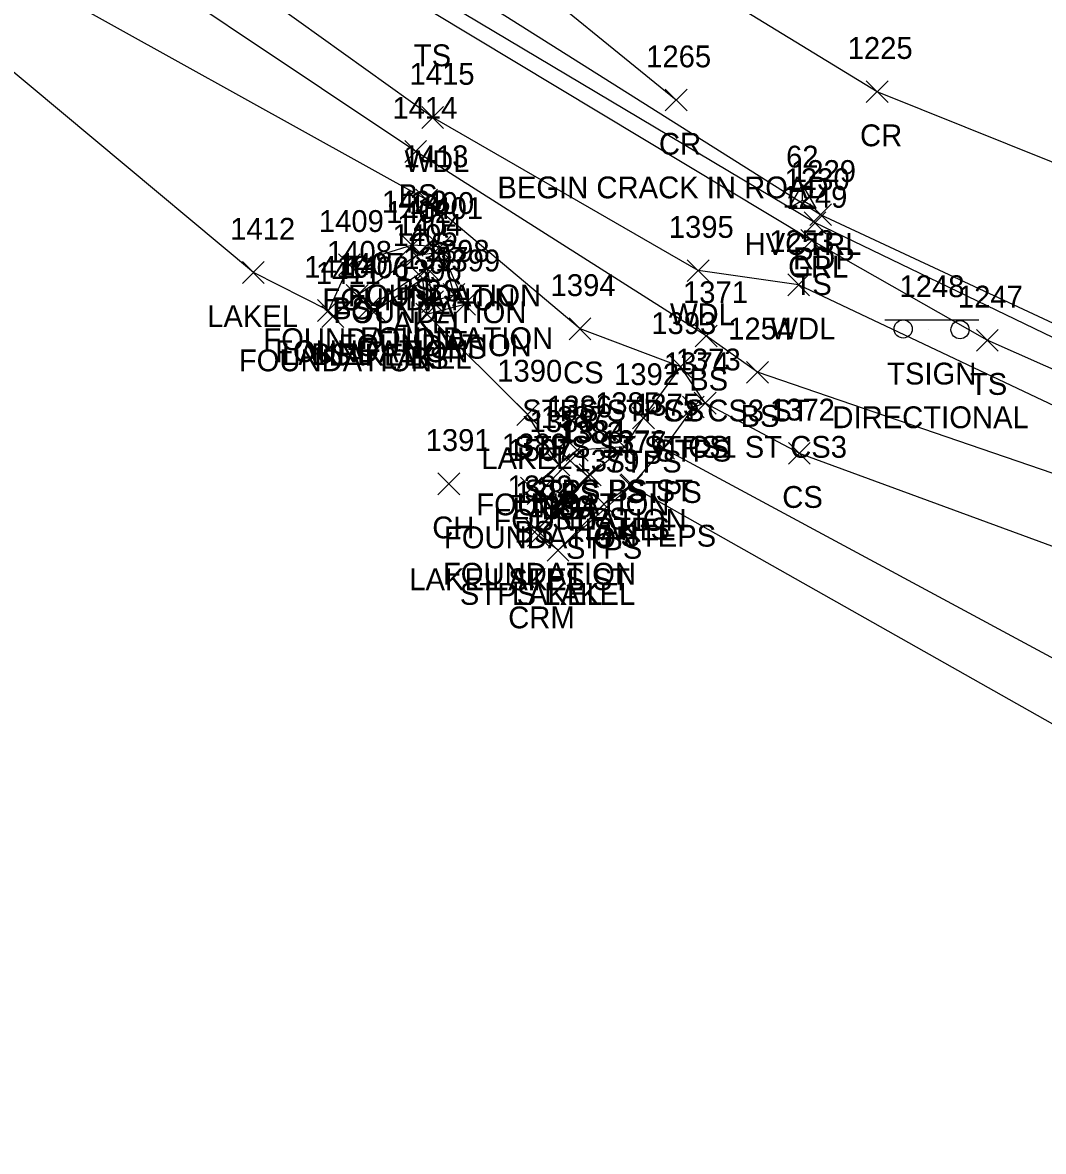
# Model space of a CAD drawing. Extents: x 1401404 to 1403982, y 557481 to 559873.
# Drawn here: x 1403210.7 to 1403304.1, y 558534.5 to 558637.9 of the extents above; entities that cross this region are included whole.
import ezdxf

# ---------------------------------------------------------------- set-up
doc = ezdxf.new("R2010")
doc.units = 0
for name, color, linetype in [('C_A', 7, 'Continuous'), ('C_I', 7, 'Continuous'), ('CPSM', 7, 'Continuous'), ('L_A', 7, 'Continuous'), ('L_C', 7, 'Continuous'), ('L_I', 7, 'Continuous'), ('L_TIC', 7, 'Continuous'), ('LAWA', 7, 'Continuous'), ('LAWE', 7, 'Continuous'), ('LBC', 7, 'Continuous'), ('LBF', 7, 'Continuous'), ('LELB', 7, 'Continuous'), ('P_A', 7, 'Continuous'), ('P_C', 7, 'Continuous'), ('P_I', 7, 'Continuous'), ('P_TIC', 7, 'Continuous'), ('PET', 7, 'Continuous'), ('PRC', 7, 'Continuous'), ('R_A', 7, 'Continuous'), ('R_I', 7, 'Continuous'), ('R_TIC', 7, 'Continuous'), ('RGR', 7, 'Continuous'), ('S_A', 7, 'Continuous'), ('S_C', 7, 'Continuous'), ('S_I', 7, 'Continuous'), ('SSGN', 7, 'Continuous')]:
    doc.layers.add(name, color=color, linetype=linetype)

msp = doc.modelspace()

# ---------------------------------------------------------------- linework, layer by layer
at = {"layer": 'CPSM'}
for p, q in [((1403280.84, 558620.92), (1403282.09, 558623.09)), ((1403283.34, 558620.92), (1403282.09, 558623.09)), ((1403282.09, 558621.65), (1403282.09, 558623.09)), ((1403280.84, 558620.92), (1403282.09, 558621.65)), ((1403282.09, 558621.65), (1403282.09, 558621.65)), ((1403282.09, 558621.65), (1403283.34, 558620.92)), ((1403280.84, 558620.92), (1403283.34, 558620.92))]:
    msp.add_line(p, q, dxfattribs=at)
at = {"layer": 'L_TIC'}
for points in [[(1403247.23, 558628.23), (1403249.23, 558630.23)], [(1403249.23, 558628.23), (1403247.23, 558630.23)], [(1403245.67, 558625.12), (1403247.67, 558627.12)], [(1403247.67, 558625.12), (1403245.67, 558627.12)], [(1403246.68, 558620.68), (1403248.68, 558622.68)], [(1403248.68, 558620.68), (1403246.68, 558622.68)], [(1403245.35, 558616.53), (1403247.35, 558618.53)], [(1403247.35, 558616.53), (1403245.35, 558618.53)], [(1403247.92, 558616.4), (1403249.92, 558618.4)], [(1403249.92, 558616.4), (1403247.92, 558618.4)], [(1403281.94, 558616.97), (1403283.94, 558618.97)], [(1403283.94, 558616.97), (1403281.94, 558618.97)], [(1403245.73, 558615.58), (1403247.73, 558617.58)], [(1403247.73, 558615.58), (1403245.73, 558617.58)], [(1403248.09, 558615.93), (1403250.09, 558617.93)], [(1403250.09, 558615.93), (1403248.09, 558617.93)], [(1403230.81, 558614.04), (1403232.81, 558616.04)], [(1403232.81, 558614.04), (1403230.81, 558616.04)], [(1403239.59, 558614.75), (1403241.59, 558616.75)], [(1403241.59, 558614.75), (1403239.59, 558616.75)], [(1403246.74, 558614.4), (1403248.74, 558616.4)], [(1403248.74, 558614.4), (1403246.74, 558616.4)], [(1403271.54, 558614.21), (1403273.54, 558616.21)], [(1403273.54, 558614.21), (1403271.54, 558616.21)], [(1403246.34, 558613.46), (1403248.34, 558615.46)], [(1403248.34, 558613.46), (1403246.34, 558615.46)], [(1403249.18, 558612.02), (1403251.18, 558614.02)], [(1403251.18, 558612.02), (1403249.18, 558614.02)], [(1403280.73, 558612.91), (1403282.73, 558614.91)], [(1403282.73, 558612.91), (1403280.73, 558614.91)], [(1403240.32, 558611.93), (1403242.32, 558613.93)], [(1403242.32, 558611.93), (1403240.32, 558613.93)], [(1403247.23, 558611.37), (1403249.23, 558613.37)], [(1403249.23, 558611.37), (1403247.23, 558613.37)], [(1403247.23, 558611.37), (1403249.23, 558613.37)], [(1403249.23, 558611.37), (1403247.23, 558613.37)], [(1403250.16, 558611.14), (1403252.16, 558613.14)], [(1403252.16, 558611.14), (1403250.16, 558613.14)], [(1403237.68, 558610.56), (1403239.68, 558612.56)], [(1403239.68, 558610.56), (1403237.68, 558612.56)], [(1403237.68, 558610.56), (1403239.68, 558612.56)], [(1403239.68, 558610.56), (1403237.68, 558612.56)], [(1403238.09, 558609.99), (1403240.09, 558611.99)], [(1403240.09, 558609.99), (1403238.09, 558611.99)], [(1403241.42, 558610.82), (1403243.42, 558612.82)], [(1403243.42, 558610.82), (1403241.42, 558612.82)], [(1403241.95, 558610.51), (1403243.95, 558612.51)], [(1403243.95, 558610.51), (1403241.95, 558612.51)], [(1403246.69, 558610.22), (1403248.69, 558612.22)], [(1403248.69, 558610.22), (1403246.69, 558612.22)], [(1403246.69, 558610.22), (1403248.69, 558612.22)], [(1403248.69, 558610.22), (1403246.69, 558612.22)], [(1403260.72, 558608.88), (1403262.72, 558610.88)], [(1403262.72, 558608.88), (1403260.72, 558610.88)], [(1403272.27, 558608.23), (1403274.27, 558610.23)], [(1403274.27, 558608.23), (1403272.27, 558610.23)], [(1403298, 558607.83), (1403300, 558609.83)], [(1403300, 558607.83), (1403298, 558609.83)], [(1403269.93, 558605.4), (1403271.93, 558607.4)], [(1403271.93, 558605.4), (1403269.93, 558607.4)], [(1403269.93, 558605.4), (1403271.93, 558607.4)], [(1403271.93, 558605.4), (1403269.93, 558607.4)], [(1403269.93, 558605.4), (1403271.93, 558607.4)], [(1403271.93, 558605.4), (1403269.93, 558607.4)], [(1403276.97, 558604.9), (1403278.97, 558606.9)], [(1403278.97, 558604.9), (1403276.97, 558606.9)], [(1403271.09, 558601.72), (1403273.09, 558603.72)], [(1403273.09, 558601.72), (1403271.09, 558603.72)], [(1403272.17, 558602.07), (1403274.17, 558604.07)], [(1403274.17, 558602.07), (1403272.17, 558604.07)], [(1403272.17, 558602.07), (1403274.17, 558604.07)], [(1403274.17, 558602.07), (1403272.17, 558604.07)], [(1403272.17, 558602.07), (1403274.17, 558604.07)], [(1403274.17, 558602.07), (1403272.17, 558604.07)], [(1403255.92, 558601.04), (1403257.92, 558603.04)], [(1403257.92, 558601.04), (1403255.92, 558603.04)], [(1403266.52, 558600.72), (1403268.52, 558602.72)], [(1403268.52, 558600.72), (1403266.52, 558602.72)], [(1403260.46, 558597.76), (1403262.46, 558599.76)], [(1403262.46, 558597.76), (1403260.46, 558599.76)], [(1403264.79, 558598.07), (1403266.79, 558600.07)], [(1403266.79, 558598.07), (1403264.79, 558600.07)], [(1403264.79, 558598.07), (1403266.79, 558600.07)], [(1403266.79, 558598.07), (1403264.79, 558600.07)], [(1403268.36, 558597.93), (1403270.36, 558599.93)], [(1403270.36, 558597.93), (1403268.36, 558599.93)], [(1403280.79, 558597.48), (1403282.79, 558599.48)], [(1403282.79, 558597.48), (1403280.79, 558599.48)], [(1403259.82, 558596.8), (1403261.82, 558598.8)], [(1403261.82, 558596.8), (1403259.82, 558598.8)], [(1403258.77, 558596.42), (1403260.77, 558598.42)], [(1403260.77, 558596.42), (1403258.77, 558598.42)], [(1403258.77, 558596.42), (1403260.77, 558598.42)], [(1403260.77, 558596.42), (1403258.77, 558598.42)], [(1403261.64, 558595.5), (1403263.64, 558597.5)], [(1403263.64, 558595.5), (1403261.64, 558597.5)], [(1403248.71, 558594.69), (1403250.71, 558596.69)], [(1403250.71, 558594.69), (1403248.71, 558596.69)], [(1403261.4, 558595.38), (1403263.4, 558597.38)], [(1403263.4, 558595.38), (1403261.4, 558597.38)], [(1403265.36, 558594.5), (1403267.36, 558596.5)], [(1403267.36, 558594.5), (1403265.36, 558596.5)], [(1403265.45, 558594.59), (1403267.45, 558596.59)], [(1403267.45, 558594.59), (1403265.45, 558596.59)], [(1403256.26, 558594.28), (1403258.26, 558596.28)], [(1403258.26, 558594.28), (1403256.26, 558596.28)], [(1403256.87, 558593.78), (1403258.87, 558595.78)], [(1403258.87, 558593.78), (1403256.87, 558595.78)], [(1403262.91, 558592.82), (1403264.91, 558594.82)], [(1403264.91, 558592.82), (1403262.91, 558594.82)], [(1403256.77, 558590.45), (1403258.77, 558592.45)], [(1403258.77, 558590.45), (1403256.77, 558592.45)], [(1403256.9, 558589.94), (1403258.9, 558591.94)], [(1403258.9, 558589.94), (1403256.9, 558591.94)], [(1403256.9, 558589.94), (1403258.9, 558591.94)], [(1403258.9, 558589.94), (1403256.9, 558591.94)], [(1403258.7, 558588.6), (1403260.7, 558590.6)], [(1403260.7, 558588.6), (1403258.7, 558590.6)], [(1403258.7, 558588.6), (1403260.7, 558590.6)], [(1403260.7, 558588.6), (1403258.7, 558590.6)]]:
    msp.add_lwpolyline(points, dxfattribs=at)
at = {"layer": 'LAWA'}
msp.add_lwpolyline([(1403316.66, 558597.36), (1403281.73, 558613.91), (1403272.54, 558615.21), (1403248.23, 558629.23), (1403213.48, 558654.18), (1403180.64, 558681.31), (1403143.75, 558710.34), (1403107.91, 558739.1), (1403071.69, 558772.58), (1403068.31, 558766.93), (1403071.88, 558756.66), (1403070.51, 558749.44)], dxfattribs=at)
at = {"layer": 'LAWE'}
for points in [[(1403238.68, 558611.56), (1403231.81, 558615.04), (1403202.57, 558639.47), (1403173.17, 558667.73), (1403127.98, 558695.57), (1403090.18, 558721.43), (1403068.99, 558749.07), (1403055.64, 558748.74), (1403047.53, 558763.16), (1403042.82, 558768.94)], [(1403259.77, 558597.42), (1403256.92, 558602.04), (1403247.69, 558611.22), (1403247.34, 558614.46), (1403242.95, 558611.51)], [(1403696.34, 558534.54), (1403680.72, 558542.26), (1403669.4, 558548.58), (1403629.67, 558556.01), (1403603.5, 558551.35), (1403567.18, 558559.29), (1403520.13, 558560.76), (1403486.9, 558558.65), (1403434.25, 558550.99), (1403410.67, 558547.97), (1403397.83, 558540.52), (1403383.21, 558537.84), (1403361.63, 558542.24), (1403347.73, 558548.91), (1403330.86, 558557.2), (1403312.09, 558569.67), (1403266.36, 558595.5), (1403259.7, 558589.6), (1403257.9, 558590.94)]]:
    msp.add_lwpolyline(points, dxfattribs=at)
at = {"layer": 'LBC'}
for points in [[(1403248.23, 558612.37), (1403250.18, 558613.02), (1403249.09, 558616.93), (1403246.73, 558616.58), (1403241.32, 558612.93), (1403239.09, 558610.99)], [(1403248.23, 558612.37), (1403247.74, 558615.4), (1403242.42, 558611.82)], [(1403257.77, 558591.45), (1403262.4, 558596.38), (1403260.82, 558597.8), (1403257.87, 558594.78)]]:
    msp.add_lwpolyline(points, dxfattribs=at)
at = {"layer": 'LBF'}
for points in [[(1403257.9, 558590.94), (1403262.64, 558596.5), (1403265.79, 558599.07), (1403267.52, 558601.72), (1403270.93, 558606.4)], [(1403273.17, 558603.07), (1403270.93, 558606.4)], [(1403273.17, 558603.07), (1403272.09, 558602.72), (1403269.36, 558598.93), (1403266.45, 558595.59), (1403263.91, 558593.82), (1403259.7, 558589.6)]]:
    msp.add_lwpolyline(points, dxfattribs=at)
at = {"layer": 'LELB'}
for points in [[(1403567.19, 558568.67), (1403521.33, 558570.05), (1403484.77, 558571.48), (1403436.83, 558574.71), (1403390.35, 558579.88), (1403360.17, 558585.19), (1403345.93, 558587.28), (1403333.51, 558592.26), (1403317.51, 558600.62), (1403299, 558608.83), (1403282.94, 558617.97), (1403248.09, 558638.93), (1403217.12, 558660.94), (1403185.33, 558684.7), (1403148.79, 558715.46), (1403112.06, 558744.49), (1403074.23, 558776.66), (1403055.65, 558783.75), (1403043.18, 558796.21), (1403041.06, 558801.07)], [(1403270.93, 558606.4), (1403261.72, 558609.88), (1403247.68, 558621.68), (1403207.96, 558643.77), (1403210.15, 558647.44), (1403209.07, 558648.44), (1403205.58, 558645.65), (1403178.43, 558674.04), (1403139.41, 558704.55), (1403100.63, 558728.29)], [(1403246.67, 558626.12), (1403212.22, 558649.17)], [(1403341.76, 558583.81), (1403338.8, 558584.67), (1403330.23, 558588.71), (1403320.84, 558584.14), (1403323.37, 558590.35), (1403277.97, 558605.9), (1403273.27, 558609.23), (1403246.67, 558626.12)], [(1403247.69, 558611.22), (1403251.16, 558612.14), (1403248.92, 558617.4), (1403246.35, 558617.53), (1403240.59, 558615.75), (1403238.68, 558611.56)], [(1403281.79, 558598.48), (1403273.17, 558603.07)], [(1403265.79, 558599.07), (1403261.46, 558598.76), (1403259.77, 558597.42), (1403257.26, 558595.28)], [(1403320.97, 558571.12), (1403269.36, 558598.93)], [(1403281.79, 558598.48), (1403320.84, 558584.14)]]:
    msp.add_lwpolyline(points, dxfattribs=at)
at = {"layer": 'P_TIC'}
for points in [[(1403287.92, 558630.6), (1403289.92, 558632.6)], [(1403289.92, 558630.6), (1403287.92, 558632.6)], [(1403269.51, 558629.83), (1403271.51, 558631.83)], [(1403271.51, 558629.83), (1403269.51, 558631.83)], [(1403282.74, 558619.33), (1403284.74, 558621.33)], [(1403284.74, 558619.33), (1403282.74, 558621.33)]]:
    msp.add_lwpolyline(points, dxfattribs=at)
at = {"layer": 'PET'}
msp.add_lwpolyline([(1403567.32, 558571.16), (1403521.05, 558571.89), (1403485.08, 558573.95), (1403437.34, 558577.29), (1403390.93, 558583.55), (1403361.61, 558591.03), (1403321.82, 558602.54), (1403283.74, 558620.33), (1403244.19, 558645.3), (1403219.22, 558663.61), (1403205.44, 558672.12), (1403186.06, 558688.41), (1403150.64, 558718.11), (1403114.18, 558748.06), (1403076.2, 558780.03), (1403043.94, 558806.7), (1402997.13, 558841.77), (1402954.25, 558870.69), (1402915.87, 558893.53), (1402876.18, 558915.42), (1402801.33, 558955.21), (1402766.49, 558972.95)], dxfattribs=at)
at = {"layer": 'PRC'}
for points in [[(1403567.87, 558582.77), (1403521.72, 558584.55), (1403486.23, 558585.01), (1403438.97, 558588.43), (1403393.1, 558594.9), (1403360.83, 558602.71), (1403288.92, 558631.6), (1403250.3, 558655.21), (1403225.89, 558672.35), (1403193.37, 558698.04), (1403157.15, 558726.96), (1403121.95, 558757.26), (1403083.22, 558789.98), (1403051.1, 558815.94), (1403004.27, 558851.49), (1402960.21, 558880.82), (1402921.63, 558903.82), (1402881.32, 558926.06), (1402807.32, 558964.73), (1402770.83, 558983.44)], [(1403270.51, 558630.83), (1403254.38, 558643.97), (1403247.18, 558647.74), (1403222.07, 558666.96), (1403211.27, 558674.34), (1403200.12, 558681.7), (1403193.45, 558684.38)]]:
    msp.add_lwpolyline(points, dxfattribs=at)
at = {"layer": 'R_TIC'}
for points in [[(1403282.23, 558618.58), (1403284.23, 558620.58)], [(1403284.23, 558618.58), (1403282.23, 558620.58)]]:
    msp.add_lwpolyline(points, dxfattribs=at)
at = {"layer": 'RGR'}
msp.add_lwpolyline([(1403343.04, 558588.83), (1403321.63, 558601.07), (1403283.23, 558619.58), (1403243.1, 558643.52), (1403218.12, 558661.74), (1403185.48, 558687.65), (1403149.87, 558716.9), (1403113.35, 558746.32), (1403075.03, 558778.37), (1403064.92, 558785.89), (1403057.13, 558787.17)], dxfattribs=at)
at = {"layer": 'SSGN'}
for p, q in [((1403289.63, 558610.7), (1403298.23, 558610.7)), ((1403293.66, 558609.8), (1403293.66, 558609.8))]:
    msp.add_line(p, q, dxfattribs=at)
for centre in [(1403291.3, 558609.87), (1403296.51, 558609.8)]:
    msp.add_circle(centre, 0.833, dxfattribs=at)

# ---------------------------------------------------------------- texts
at = {"layer": 'C_A'}
msp.add_text('HVCTRL', height=2, dxfattribs=at).set_placement((1403276.78, 558616.65))
at = {"layer": 'C_I'}
msp.add_text('62', height=2, dxfattribs=at).set_placement((1403280.58, 558624.65))
at = {"layer": 'L_A'}
for s, p in [('TS', (1403246.5, 558633.93)), ('WDL', (1403245.65, 558624.23)), ('BS', (1403245.11, 558621.12)), ('CS', (1403246.12, 558616.68)), ('TS', (1403281.35, 558612.97)), ('FOUNDATION', (1403240.48, 558611.93)), ('BS', (1403244.79, 558612.53)), ('BS', (1403247.36, 558612.4)), ('FOUNDATION', (1403238.13, 558611.58)), ('LAKEL', (1403227.58, 558610.04)), ('BS', (1403239.03, 558610.75)), ('FOUNDATION', (1403239.13, 558610.4)), ('WDL', (1403269.95, 558610.21)), ('LAKEL', (1403243.1, 558609.46)), ('WDL', (1403279.15, 558608.91)), ('FOUNDATION', (1403232.72, 558607.93)), ('FOUNDATION', (1403241.58, 558608.02)), ('FOUNDATION', (1403233.81, 558606.82)), ('FOUNDATION', (1403239.62, 558607.37)), ('FOUNDATION', (1403239.62, 558607.37)), ('BS', (1403249.6, 558607.14)), ('FOUNDATION', (1403230.48, 558605.99)), ('LAKEL', (1403234.44, 558606.56)), ('BS', (1403237.12, 558606.56)), ('LAKEL', (1403238.71, 558606.51)), ('LAKEL', (1403243.46, 558606.22)), ('BS', (1403246.13, 558606.22)), ('CS', (1403260.16, 558604.88)), ('BS', (1403271.71, 558604.23)), ('TS', (1403297.41, 558603.83)), ('STPS STPS1 CS3 ST', (1403256.42, 558601.4)), ('STPS STPS1 CS3 ST', (1403256.42, 558601.4)), ('CS', (1403269.37, 558601.4)), ('BS', (1403276.41, 558600.9)), ('STPS ST STPS1 ST CS3', (1403255.69, 558598.07)), ('STPS ST STPS1 ST CS3', (1403255.69, 558598.07)), ('STPS', (1403268.61, 558597.72)), ('CS', (1403271.61, 558598.07)), ('LAKEL', (1403252.68, 558597.04)), ('STPS', (1403264.04, 558596.72)), ('STPS BS ST', (1403256.6, 558594.07)), ('BS', (1403259.9, 558593.76)), ('BS', (1403264.23, 558594.07)), ('STPS', (1403265.88, 558593.93)), ('CS', (1403280.23, 558593.48)), ('FOUNDATION', (1403252.22, 558592.8)), ('LAKEL', (1403255.54, 558592.42)), ('BS', (1403258.21, 558592.42)), ('FOUNDATION', (1403253.79, 558591.38)), ('STPS', (1403259.16, 558591.5)), ('CH', (1403248.19, 558590.69)), ('BS', (1403255.7, 558590.28)), ('LAKEL', (1403262.12, 558590.5)), ('STPS', (1403262.97, 558590.59)), ('FOUNDATION', (1403249.26, 558589.78)), ('STPS', (1403260.43, 558588.82)), ('FOUNDATION', (1403249.16, 558586.45)), ('LAKEL STPS ST', (1403246.08, 558585.94)), ('LAKEL', (1403253.66, 558585.94)), ('STPS LAKEL', (1403250.71, 558584.6)), ('LAKEL', (1403255.47, 558584.6))]:
    msp.add_text(s, height=2, dxfattribs=at).set_placement(p)
at = {"layer": 'L_C'}
for s, p in [('5 STEPS', (1403263.18, 558589.93)), ('CRM', (1403255.14, 558582.45))]:
    msp.add_text(s, height=2, dxfattribs=at).set_placement(p)
at = {"layer": 'L_I'}
for s, p in [('1415', (1403246.11, 558632.23)), ('1414', (1403244.54, 558629.12)), ('1413', (1403245.55, 558624.68)), ('1403', (1403243.58, 558620.53)), ('1400', (1403246.07, 558620.4)), ('1249', (1403280.24, 558620.97)), ('1402', (1403243.96, 558619.58)), ('1401', (1403246.89, 558619.93)), ('1409', (1403237.81, 558618.75)), ('1404', (1403244.97, 558618.4)), ('1395', (1403269.84, 558618.21)), ('1412', (1403229.69, 558618.04)), ('1405', (1403244.56, 558617.46)), ('1253', (1403279.04, 558616.91)), ('1408', (1403238.55, 558615.93)), ('1397', (1403245.54, 558615.37)), ('1397', (1403245.54, 558615.37)), ('1398', (1403247.49, 558616.02)), ('1399', (1403248.46, 558615.14)), ('1410', (1403236.47, 558614.56)), ('1410', (1403236.47, 558614.56)), ('1407', (1403239.65, 558614.82)), ('1406', (1403240.12, 558614.51)), ('1396', (1403244.94, 558614.22)), ('1396', (1403244.94, 558614.22)), ('1411', (1403237.53, 558613.99)), ('1394', (1403259.02, 558612.88)), ('1371', (1403271.14, 558612.23)), ('1247', (1403296.31, 558611.83)), ('1393', (1403268.24, 558609.4)), ('1393', (1403268.24, 558609.4)), ('1393', (1403268.24, 558609.4)), ('1254', (1403275.28, 558608.9)), ('1374', (1403269.4, 558605.72)), ('1373', (1403270.48, 558606.07)), ('1373', (1403270.48, 558606.07)), ('1373', (1403270.48, 558606.07)), ('1390', (1403254.14, 558605.04)), ('1392', (1403264.83, 558604.72)), ('1386', (1403258.71, 558601.76)), ('1385', (1403263.09, 558602.07)), ('1385', (1403263.09, 558602.07)), ('1375', (1403266.67, 558601.93)), ('1387', (1403258.13, 558600.8)), ('1372', (1403279.1, 558601.48)), ('1388', (1403257.08, 558600.42)), ('1388', (1403257.08, 558600.42)), ('1391', (1403247.58, 558598.69)), ('1383', (1403259.7, 558599.38)), ('1384', (1403259.95, 558599.5)), ('1377', (1403263.67, 558598.5)), ('1376', (1403263.7, 558598.59)), ('1389', (1403254.56, 558598.28)), ('1507', (1403255.09, 558597.78)), ('1379', (1403261.21, 558596.82)), ('1382', (1403255.08, 558594.45)), ('1381', (1403255.77, 558593.94)), ('1381', (1403255.77, 558593.94)), ('1380', (1403256.92, 558592.6)), ('1380', (1403256.92, 558592.6))]:
    msp.add_text(s, height=2, dxfattribs=at).set_placement(p)
at = {"layer": 'P_A'}
for s, p in [('CR', (1403287.35, 558626.6)), ('CR', (1403268.94, 558625.83)), ('RDP', (1403281.22, 558615.33))]:
    msp.add_text(s, height=2, dxfattribs=at).set_placement(p)
at = {"layer": 'P_C'}
msp.add_text('BEGIN CRACK IN ROAD', height=2, dxfattribs=at).set_placement((1403254.15, 558621.83))
at = {"layer": 'P_I'}
for s, p in [('1265', (1403267.77, 558633.83)), ('1225', (1403286.22, 558634.6)), ('1229', (1403281.03, 558623.33))]:
    msp.add_text(s, height=2, dxfattribs=at).set_placement(p)
at = {"layer": 'R_A'}
msp.add_text('GRL', height=2, dxfattribs=at).set_placement((1403280.77, 558614.58))
at = {"layer": 'R_I'}
msp.add_text('1230', height=2, dxfattribs=at).set_placement((1403280.45, 558622.58))
at = {"layer": 'S_A'}
msp.add_text('TSIGN', height=2, dxfattribs=at).set_placement((1403289.83, 558604.78))
at = {"layer": 'S_C'}
msp.add_text('DIRECTIONAL', height=2, dxfattribs=at).set_placement((1403284.82, 558600.78))
at = {"layer": 'S_I'}
msp.add_text('1248', height=2, dxfattribs=at).set_placement((1403290.96, 558612.78))

doc.saveas('drawing.dxf')
